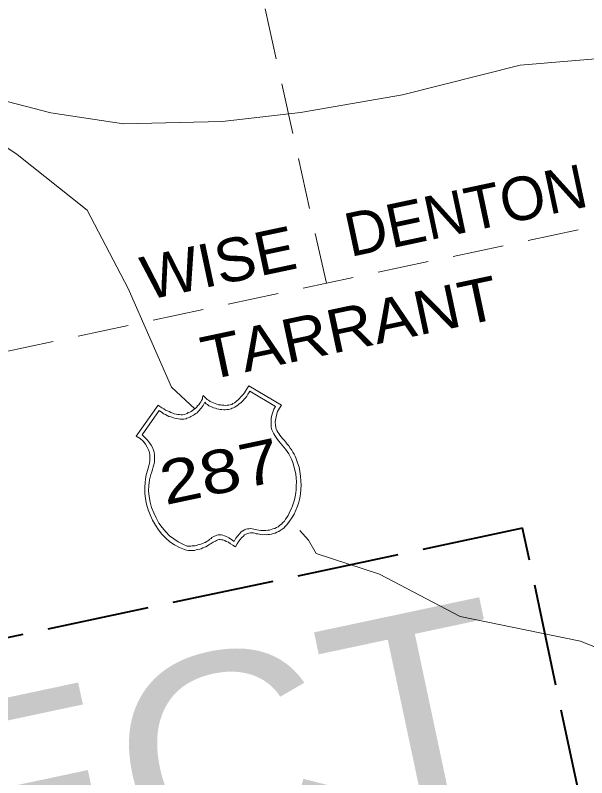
# Model space of a CAD drawing. Extents: x 2357218 to 2371708, y 6973728 to 6980157.
# Drawn here: x 2357388.5 to 2357455.6, y 6974746.8 to 6974836.3 of the extents above; entities that cross this region are included whole.
import ezdxf

# ---------------------------------------------------------------- set-up
doc = ezdxf.new("R2010")
doc.units = 0
doc.header["$LTSCALE"] = 2
doc.linetypes.add('LONG_DASHED', pattern=[7.5, 6, -1.5])
doc.linetypes.add('MEDIUM_DASHED', pattern=[4.5, 3, -1.5])
doc.layers.add('62', color=7, linetype='Continuous', lineweight=13)
doc.layers.add('63', color=7, linetype='Continuous', lineweight=13)

msp = doc.modelspace()

# ---------------------------------------------------------------- linework, layer by layer
at = {"layer": '62', "linetype": 'MEDIUM_DASHED'}
for p, q in [((2357425, 6974804.799), (2357404.314, 6974897.367)), ((2357701.055, 6974863.476), (2357262.587, 6974770.278))]:
    msp.add_line(p, q, dxfattribs=at)
at = {"layer": '62'}
for p, q in [((2357406.798, 6974792.604), (2357409.547, 6974790.06)), ((2357422.92, 6974774.658), (2357421.873, 6974775.793))]:
    msp.add_line(p, q, dxfattribs=at)
for points in [[(2357340.901, 6974883.89), (2357347.602, 6974879.103), (2357357.079, 6974868.946), (2357365.551, 6974857.313), (2357370.799, 6974843.455), (2357373.187, 6974835.471), (2357378.836, 6974826.528), (2357388.708, 6974819.907), (2357396.909, 6974813.368), (2357401.732, 6974804.203), (2357406.798, 6974792.604)], [(2357316.634, 6974822.183), (2357325.977, 6974829.21), (2357339.57, 6974833.985), (2357356.843, 6974830.109), (2357367.736, 6974831.46), (2357382.508, 6974827.444), (2357392.662, 6974824.794), (2357401.195, 6974823.527), (2357412.755, 6974823.776), (2357421.962, 6974824.837), (2357433.942, 6974826.923), (2357447.739, 6974830.408), (2357465.936, 6974831.929), (2357477.637, 6974833.588), (2357491.11, 6974834.819), (2357506.983, 6974831.471), (2357522.127, 6974827.953), (2357536.104, 6974824.115), (2357552.75, 6974816.152), (2357563.852, 6974811.216), (2357577.192, 6974806.369), (2357585.353, 6974801.086)], [(2357402.679, 6974786.874), (2357405.245, 6974790.503), (2357405.462, 6974790.341), (2357405.682, 6974790.181), (2357405.914, 6974790.069), (2357406.102, 6974789.926), (2357406.329, 6974789.838), (2357406.534, 6974789.741), (2357406.738, 6974789.647), (2357406.963, 6974789.557), (2357407.143, 6974789.479), (2357407.355, 6974789.456), (2357407.546, 6974789.404), (2357407.755, 6974789.403), (2357407.945, 6974789.374), (2357408.108, 6974789.364), (2357408.33, 6974789.411), (2357408.523, 6974789.474), (2357408.649, 6974789.523), (2357408.791, 6974789.623), (2357408.963, 6974789.681), (2357409.128, 6974789.762), (2357409.283, 6974789.889), (2357409.425, 6974789.988), (2357409.583, 6974790.113), (2357409.74, 6974790.239), (2357409.867, 6974790.404), (2357410.019, 6974790.551), (2357410.142, 6974790.736), (2357410.272, 6974790.881), (2357410.347, 6974791.058), (2357410.45, 6974791.239), (2357410.476, 6974791.431), (2357410.547, 6974791.63), (2357410.695, 6974791.478), (2357410.843, 6974791.323), (2357411.013, 6974791.177), (2357411.172, 6974791.072), (2357411.364, 6974790.929), (2357411.562, 6974790.856), (2357411.746, 6974790.756), (2357411.948, 6974790.685), (2357412.141, 6974790.634), (2357412.319, 6974790.555), (2357412.552, 6974790.537), (2357412.718, 6974790.504), (2357412.972, 6974790.512), (2357413.139, 6974790.477), (2357413.369, 6974790.482), (2357413.545, 6974790.519), (2357413.7, 6974790.55), (2357413.898, 6974790.592), (2357414.014, 6974790.687), (2357414.204, 6974790.774), (2357414.362, 6974790.899), (2357414.501, 6974790.996), (2357414.632, 6974791.141), (2357414.806, 6974791.292), (2357414.937, 6974791.436), (2357415.085, 6974791.605), (2357415.214, 6974791.769), (2357415.376, 6974791.965), (2357415.498, 6974792.153), (2357415.641, 6974792.345), (2357415.756, 6974792.553), (2357415.897, 6974792.767), (2357419.715, 6974790.495), (2357419.488, 6974790.147), (2357419.273, 6974789.756), (2357419.154, 6974789.342), (2357419.081, 6974788.937), (2357419.006, 6974788.528), (2357419.017, 6974788.162), (2357419.076, 6974787.875), (2357419.118, 6974787.678), (2357419.193, 6974787.532), (2357419.302, 6974787.347), (2357419.406, 6974787.187), (2357419.541, 6974786.985), (2357419.696, 6974786.786), (2357419.853, 6974786.592), (2357420.04, 6974786.379), (2357420.225, 6974786.142), (2357420.41, 6974785.926), (2357420.592, 6974785.712), (2357420.764, 6974785.451), (2357420.926, 6974785.232), (2357421.072, 6974784.987), (2357421.209, 6974784.764), (2357421.327, 6974784.534), (2357421.422, 6974784.303), (2357421.61, 6974783.745), (2357421.793, 6974783.208), (2357421.901, 6974782.702), (2357421.947, 6974782.157), (2357422.012, 6974781.64), (2357422.029, 6974781.117), (2357422.001, 6974780.605), (2357421.95, 6974780.088), (2357421.894, 6974779.591), (2357421.766, 6974779.105)], [(2357420.765, 6974778.088), (2357420.912, 6974778.371), (2357421.025, 6974778.694), (2357421.138, 6974779.039), (2357421.245, 6974779.409), (2357421.323, 6974779.794), (2357421.396, 6974780.2), (2357421.443, 6974780.624), (2357421.47, 6974781.046), (2357421.486, 6974781.507), (2357421.439, 6974781.959), (2357421.41, 6974782.413), (2357421.308, 6974782.896), (2357421.185, 6974783.355), (2357421.049, 6974783.785), (2357420.924, 6974784.15), (2357420.74, 6974784.48), (2357420.582, 6974784.791), (2357420.385, 6974785.07), (2357420.208, 6974785.356), (2357420.021, 6974785.592), (2357419.81, 6974785.823), (2357419.6, 6974786.054), (2357419.419, 6974786.268), (2357419.256, 6974786.488), (2357419.093, 6974786.706), (2357418.932, 6974786.927), (2357418.814, 6974787.153), (2357418.703, 6974787.359), (2357418.602, 6974787.614), (2357418.51, 6974787.938), (2357418.506, 6974788.284), (2357418.502, 6974788.629), (2357418.518, 6974788.976), (2357418.582, 6974789.333), (2357418.694, 6974789.681), (2357418.85, 6974790.015), (2357419.011, 6974790.346), (2357416.005, 6974792.146), (2357415.885, 6974791.957), (2357415.783, 6974791.776), (2357415.667, 6974791.567), (2357415.543, 6974791.402), (2357415.395, 6974791.232), (2357415.247, 6974791.063), (2357415.094, 6974790.917), (2357414.942, 6974790.768), (2357414.763, 6974790.639), (2357414.608, 6974790.492), (2357414.425, 6974790.383), (2357414.261, 6974790.279), (2357414.096, 6974790.199), (2357413.946, 6974790.142), (2357413.803, 6974790.066), (2357413.65, 6974790.034), (2357413.494, 6974790), (2357413.313, 6974789.985), (2357413.11, 6974789.967), (2357412.952, 6974789.953), (2357412.718, 6974789.975), (2357412.55, 6974790.007), (2357412.362, 6974790.037), (2357412.143, 6974790.082), (2357411.972, 6974790.137), (2357411.754, 6974790.182), (2357411.597, 6974790.266), (2357411.421, 6974790.344), (2357411.215, 6974790.437), (2357411.049, 6974790.563), (2357410.89, 6974790.667), (2357410.717, 6974790.839), (2357410.622, 6974790.632), (2357410.523, 6974790.451), (2357410.418, 6974790.29), (2357410.311, 6974790.153), (2357410.175, 6974790.032), (2357410.088, 6974789.901), (2357409.938, 6974789.75), (2357409.826, 6974789.613), (2357409.683, 6974789.535), (2357409.526, 6974789.409), (2357409.402, 6974789.339), (2357409.24, 6974789.234), (2357409.09, 6974789.181), (2357408.952, 6974789.081), (2357408.78, 6974789.023), (2357408.63, 6974788.966), (2357408.483, 6974788.911), (2357408.262, 6974788.864), (2357408.054, 6974788.868), (2357407.826, 6974788.866), (2357407.634, 6974788.895), (2357407.394, 6974788.934), (2357407.154, 6974788.975), (2357406.98, 6974789.054), (2357406.736, 6974789.116), (2357406.515, 6974789.185), (2357406.309, 6974789.28), (2357406.124, 6974789.4), (2357405.896, 6974789.489), (2357405.706, 6974789.634)], [(2357405.379, 6974789.863), (2357403.36, 6974787.018), (2357403.699, 6974786.723), (2357404, 6974786.396), (2357404.224, 6974786.099), (2357404.443, 6974785.822), (2357404.575, 6974785.529), (2357404.707, 6974785.234), (2357404.784, 6974784.976), (2357404.824, 6974784.684), (2357404.818, 6974784.384), (2357404.831, 6974784.11), (2357404.804, 6974783.807), (2357404.729, 6974783.515), (2357404.669, 6974783.249), (2357404.594, 6974782.957), (2357404.491, 6974782.682), (2357404.392, 6974782.384), (2357404.228, 6974781.752), (2357404.164, 6974781.072), (2357404.133, 6974780.467), (2357404.209, 6974779.794), (2357404.326, 6974779.126), (2357404.484, 6974778.492), (2357404.734, 6974777.852), (2357404.998, 6974777.266), (2357405.331, 6974776.671), (2357405.722, 6974776.13), (2357406.152, 6974775.626), (2357406.591, 6974775.167), (2357407.084, 6974774.811), (2357407.594, 6974774.46), (2357408.137, 6974774.184), (2357408.666, 6974773.975), (2357408.781, 6974773.975), (2357408.928, 6974773.937), (2357409.085, 6974773.949), (2357409.261, 6974773.985), (2357409.399, 6974773.992), (2357409.58, 6974774.006), (2357409.756, 6974774.043), (2357409.925, 6974774.104), (2357410.12, 6974774.169), (2357410.274, 6974774.201), (2357410.463, 6974774.286), (2357410.634, 6974774.346), (2357410.784, 6974774.402), (2357410.946, 6974774.504), (2357411.089, 6974774.58), (2357411.215, 6974774.654), (2357411.325, 6974774.769), (2357411.466, 6974774.867), (2357411.563, 6974774.957), (2357411.702, 6974775.057), (2357411.847, 6974775.132), (2357411.973, 6974775.183), (2357412.123, 6974775.239), (2357412.278, 6974775.271), (2357412.437, 6974775.281), (2357412.644, 6974775.281), (2357412.834, 6974775.252), (2357413.038, 6974775.157), (2357413.281, 6974775.092), (2357413.549, 6974774.919), (2357413.859, 6974774.755), (2357414.163, 6974774.52), (2357414.383, 6974774.89), (2357414.6, 6974775.165), (2357414.801, 6974775.415), (2357415.009, 6974775.62), (2357415.189, 6974775.752), (2357415.373, 6974775.861), (2357415.54, 6974775.941), (2357415.759, 6974775.988), (2357415.918, 6974775.997), (2357416.079, 6974776.011), (2357416.289, 6974775.984), (2357416.479, 6974775.957), (2357416.647, 6974775.924), (2357416.844, 6974775.873), (2357417.054, 6974775.848), (2357417.27, 6974775.802), (2357417.479, 6974775.8), (2357417.691, 6974775.778), (2357417.893, 6974775.797), (2357418.119, 6974775.823), (2357418.321, 6974775.841), (2357418.535, 6974775.911), (2357418.73, 6974775.975), (2357418.944, 6974776.044), (2357419.152, 6974776.157), (2357419.34, 6974776.242), (2357419.531, 6974776.422), (2357419.712, 6974776.552), (2357419.881, 6974776.727), (2357420.072, 6974776.905), (2357420.211, 6974777.118), (2357420.373, 6974777.336), (2357420.512, 6974777.549), (2357420.636, 6974777.83), (2357420.765, 6974778.088)], [(2357405.706, 6974789.634), (2357405.54, 6974789.76), (2357405.379, 6974789.863)], [(2357403.476, 6974786.263), (2357403.132, 6974786.58), (2357402.679, 6974786.874)], [(2357421.766, 6974779.105), (2357421.614, 6974778.636), (2357421.413, 6974778.179), (2357421.231, 6974777.727), (2357420.934, 6974777.295), (2357420.678, 6974776.872), (2357420.351, 6974776.459), (2357420.165, 6974776.258), (2357419.993, 6974776.083), (2357419.793, 6974775.949), (2357419.593, 6974775.813), (2357419.414, 6974775.683), (2357419.202, 6974775.591), (2357418.969, 6974775.498), (2357418.778, 6974775.432), (2357418.538, 6974775.358), (2357418.312, 6974775.334), (2357418.11, 6974775.315), (2357417.929, 6974775.3), (2357417.698, 6974775.318), (2357417.515, 6974775.304), (2357417.323, 6974775.331), (2357417.131, 6974775.382), (2357416.945, 6974775.389), (2357416.755, 6974775.418), (2357416.603, 6974775.478), (2357416.413, 6974775.506), (2357416.279, 6974775.501), (2357416.092, 6974775.506), (2357415.909, 6974775.49), (2357415.759, 6974775.458), (2357415.59, 6974775.377), (2357415.406, 6974775.269), (2357415.256, 6974775.122), (2357415.079, 6974774.97), (2357414.898, 6974774.748), (2357414.714, 6974774.523), (2357414.527, 6974774.21), (2357414.326, 6974773.867), (2357414.004, 6974774.074), (2357413.738, 6974774.248), (2357413.492, 6974774.424), (2357413.245, 6974774.511), (2357413.06, 6974774.61), (2357412.863, 6974774.683), (2357412.694, 6974774.716), (2357412.531, 6974774.725), (2357412.395, 6974774.721), (2357412.24, 6974774.687), (2357412.114, 6974774.638), (2357411.969, 6974774.561), (2357411.864, 6974774.516), (2357411.72, 6974774.44), (2357411.578, 6974774.341), (2357411.456, 6974774.268), (2357411.337, 6974774.175), (2357411.192, 6974774.097), (2357411.03, 6974773.993), (2357410.848, 6974773.887), (2357410.677, 6974773.827), (2357410.489, 6974773.741), (2357410.296, 6974773.654), (2357410.125, 6974773.594), (2357409.908, 6974773.548), (2357409.708, 6974773.506), (2357409.511, 6974773.464), (2357409.262, 6974773.434), (2357409.052, 6974773.458), (2357408.822, 6974773.454), (2357408.58, 6974773.497), (2357408.338, 6974773.558), (2357407.762, 6974773.783), (2357407.189, 6974774.097), (2357406.629, 6974774.46), (2357406.147, 6974774.888), (2357405.678, 6974775.364), (2357405.274, 6974775.853), (2357404.926, 6974776.421), (2357404.591, 6974777.017), (2357404.3, 6974777.624), (2357404.081, 6974778.223), (2357403.896, 6974778.872), (2357403.76, 6974779.512), (2357403.686, 6974780.187), (2357403.669, 6974780.805), (2357403.71, 6974781.48), (2357403.815, 6974782.078), (2357403.855, 6974782.317), (2357403.917, 6974782.561), (2357403.999, 6974782.83), (2357404.079, 6974783.099), (2357404.155, 6974783.393), (2357404.233, 6974783.684), (2357404.279, 6974783.994), (2357404.285, 6974784.295), (2357404.288, 6974784.617), (2357404.216, 6974784.946), (2357404.129, 6974785.249), (2357403.966, 6974785.584), (2357403.756, 6974785.907), (2357403.476, 6974786.263)], [(2357422.92, 6974774.658), (2357423.803, 6974773.097), (2357431.242, 6974770.675), (2357440.696, 6974765.714), (2357454.819, 6974762.805), (2357466.769, 6974757.982), (2357474.201, 6974755.812)]]:
    msp.add_lwpolyline(points, dxfattribs=at)
at = {"layer": '62', "linetype": 'LONG_DASHED', "lineweight": 40}
msp.add_lwpolyline([(2357277.991, 6974739.919), (2357291.257, 6974677.497), (2357461.31, 6974713.643), (2357448.042, 6974776.064), (2357277.682, 6974739.853)], dxfattribs=at)
at = {"layer": '63', "linetype": 'MEDIUM_DASHED'}
for p, q in [((2357425, 6974804.799), (2357404.314, 6974897.367)), ((2357701.055, 6974863.476), (2357262.587, 6974770.278))]:
    msp.add_line(p, q, dxfattribs=at)
at = {"layer": '63'}
for p, q in [((2357406.798, 6974792.604), (2357409.547, 6974790.06)), ((2357422.92, 6974774.658), (2357421.873, 6974775.793))]:
    msp.add_line(p, q, dxfattribs=at)
for points in [[(2357340.901, 6974883.89), (2357347.602, 6974879.103), (2357357.079, 6974868.946), (2357365.551, 6974857.313), (2357370.799, 6974843.455), (2357373.187, 6974835.471), (2357378.836, 6974826.528), (2357388.708, 6974819.907), (2357396.909, 6974813.368), (2357401.732, 6974804.203), (2357406.798, 6974792.604)], [(2357316.634, 6974822.183), (2357325.977, 6974829.21), (2357339.57, 6974833.985), (2357356.843, 6974830.109), (2357367.736, 6974831.46), (2357382.508, 6974827.444), (2357392.662, 6974824.794), (2357401.195, 6974823.527), (2357412.755, 6974823.776), (2357421.962, 6974824.837), (2357433.942, 6974826.923), (2357447.739, 6974830.408), (2357465.936, 6974831.929), (2357477.637, 6974833.588), (2357491.11, 6974834.819), (2357506.983, 6974831.471), (2357522.127, 6974827.953), (2357536.104, 6974824.115), (2357552.75, 6974816.152), (2357563.852, 6974811.216), (2357577.192, 6974806.369), (2357585.353, 6974801.086)], [(2357402.679, 6974786.874), (2357405.245, 6974790.503), (2357405.462, 6974790.341), (2357405.682, 6974790.181), (2357405.914, 6974790.069), (2357406.102, 6974789.926), (2357406.329, 6974789.838), (2357406.534, 6974789.741), (2357406.738, 6974789.647), (2357406.963, 6974789.557), (2357407.143, 6974789.479), (2357407.355, 6974789.456), (2357407.546, 6974789.404), (2357407.755, 6974789.403), (2357407.945, 6974789.374), (2357408.108, 6974789.364), (2357408.33, 6974789.411), (2357408.523, 6974789.474), (2357408.649, 6974789.523), (2357408.791, 6974789.623), (2357408.963, 6974789.681), (2357409.128, 6974789.762), (2357409.283, 6974789.889), (2357409.425, 6974789.988), (2357409.583, 6974790.113), (2357409.74, 6974790.239), (2357409.867, 6974790.404), (2357410.019, 6974790.551), (2357410.142, 6974790.736), (2357410.272, 6974790.881), (2357410.347, 6974791.058), (2357410.45, 6974791.239), (2357410.476, 6974791.431), (2357410.547, 6974791.63), (2357410.695, 6974791.478), (2357410.843, 6974791.323), (2357411.013, 6974791.177), (2357411.172, 6974791.072), (2357411.364, 6974790.929), (2357411.562, 6974790.856), (2357411.746, 6974790.756), (2357411.948, 6974790.685), (2357412.141, 6974790.634), (2357412.319, 6974790.555), (2357412.552, 6974790.537), (2357412.718, 6974790.504), (2357412.972, 6974790.512), (2357413.139, 6974790.477), (2357413.369, 6974790.482), (2357413.545, 6974790.519), (2357413.7, 6974790.55), (2357413.898, 6974790.592), (2357414.014, 6974790.687), (2357414.204, 6974790.774), (2357414.362, 6974790.899), (2357414.501, 6974790.996), (2357414.632, 6974791.141), (2357414.806, 6974791.292), (2357414.937, 6974791.436), (2357415.085, 6974791.605), (2357415.214, 6974791.769), (2357415.376, 6974791.965), (2357415.498, 6974792.153), (2357415.641, 6974792.345), (2357415.756, 6974792.553), (2357415.897, 6974792.767), (2357419.715, 6974790.495), (2357419.488, 6974790.147), (2357419.273, 6974789.756), (2357419.154, 6974789.342), (2357419.081, 6974788.937), (2357419.006, 6974788.528), (2357419.017, 6974788.162), (2357419.076, 6974787.875), (2357419.118, 6974787.678), (2357419.193, 6974787.532), (2357419.302, 6974787.347), (2357419.406, 6974787.187), (2357419.541, 6974786.985), (2357419.696, 6974786.786), (2357419.853, 6974786.592), (2357420.04, 6974786.379), (2357420.225, 6974786.142), (2357420.41, 6974785.926), (2357420.592, 6974785.712), (2357420.764, 6974785.451), (2357420.926, 6974785.232), (2357421.072, 6974784.987), (2357421.209, 6974784.764), (2357421.327, 6974784.534), (2357421.422, 6974784.303), (2357421.61, 6974783.745), (2357421.793, 6974783.208), (2357421.901, 6974782.702), (2357421.947, 6974782.157), (2357422.012, 6974781.64), (2357422.029, 6974781.117), (2357422.001, 6974780.605), (2357421.95, 6974780.088), (2357421.894, 6974779.591), (2357421.766, 6974779.105)], [(2357420.765, 6974778.088), (2357420.912, 6974778.371), (2357421.025, 6974778.694), (2357421.138, 6974779.039), (2357421.245, 6974779.409), (2357421.323, 6974779.794), (2357421.396, 6974780.2), (2357421.443, 6974780.624), (2357421.47, 6974781.046), (2357421.486, 6974781.507), (2357421.439, 6974781.959), (2357421.41, 6974782.413), (2357421.308, 6974782.896), (2357421.185, 6974783.355), (2357421.049, 6974783.785), (2357420.924, 6974784.15), (2357420.74, 6974784.48), (2357420.582, 6974784.791), (2357420.385, 6974785.07), (2357420.208, 6974785.356), (2357420.021, 6974785.592), (2357419.81, 6974785.823), (2357419.6, 6974786.054), (2357419.419, 6974786.268), (2357419.256, 6974786.488), (2357419.093, 6974786.706), (2357418.932, 6974786.927), (2357418.814, 6974787.153), (2357418.703, 6974787.359), (2357418.602, 6974787.614), (2357418.51, 6974787.938), (2357418.506, 6974788.284), (2357418.502, 6974788.629), (2357418.518, 6974788.976), (2357418.582, 6974789.333), (2357418.694, 6974789.681), (2357418.85, 6974790.015), (2357419.011, 6974790.346), (2357416.005, 6974792.146), (2357415.885, 6974791.957), (2357415.783, 6974791.776), (2357415.667, 6974791.567), (2357415.543, 6974791.402), (2357415.395, 6974791.232), (2357415.247, 6974791.063), (2357415.094, 6974790.917), (2357414.942, 6974790.768), (2357414.763, 6974790.639), (2357414.608, 6974790.492), (2357414.425, 6974790.383), (2357414.261, 6974790.279), (2357414.096, 6974790.199), (2357413.946, 6974790.142), (2357413.803, 6974790.066), (2357413.65, 6974790.034), (2357413.494, 6974790), (2357413.313, 6974789.985), (2357413.11, 6974789.967), (2357412.952, 6974789.953), (2357412.718, 6974789.975), (2357412.55, 6974790.007), (2357412.362, 6974790.037), (2357412.143, 6974790.082), (2357411.972, 6974790.137), (2357411.754, 6974790.182), (2357411.597, 6974790.266), (2357411.421, 6974790.344), (2357411.215, 6974790.437), (2357411.049, 6974790.563), (2357410.89, 6974790.667), (2357410.717, 6974790.839), (2357410.622, 6974790.632), (2357410.523, 6974790.451), (2357410.418, 6974790.29), (2357410.311, 6974790.153), (2357410.175, 6974790.032), (2357410.088, 6974789.901), (2357409.938, 6974789.75), (2357409.826, 6974789.613), (2357409.683, 6974789.535), (2357409.526, 6974789.409), (2357409.402, 6974789.339), (2357409.24, 6974789.234), (2357409.09, 6974789.181), (2357408.952, 6974789.081), (2357408.78, 6974789.023), (2357408.63, 6974788.966), (2357408.483, 6974788.911), (2357408.262, 6974788.864), (2357408.054, 6974788.868), (2357407.826, 6974788.866), (2357407.634, 6974788.895), (2357407.394, 6974788.934), (2357407.154, 6974788.975), (2357406.98, 6974789.054), (2357406.736, 6974789.116), (2357406.515, 6974789.185), (2357406.309, 6974789.28), (2357406.124, 6974789.4), (2357405.896, 6974789.489), (2357405.706, 6974789.634)], [(2357405.379, 6974789.863), (2357403.36, 6974787.018), (2357403.699, 6974786.723), (2357404, 6974786.396), (2357404.224, 6974786.099), (2357404.443, 6974785.822), (2357404.575, 6974785.529), (2357404.707, 6974785.234), (2357404.784, 6974784.976), (2357404.824, 6974784.684), (2357404.818, 6974784.384), (2357404.831, 6974784.11), (2357404.804, 6974783.807), (2357404.729, 6974783.515), (2357404.669, 6974783.249), (2357404.594, 6974782.957), (2357404.491, 6974782.682), (2357404.392, 6974782.384), (2357404.228, 6974781.752), (2357404.164, 6974781.072), (2357404.133, 6974780.467), (2357404.209, 6974779.794), (2357404.326, 6974779.126), (2357404.484, 6974778.492), (2357404.734, 6974777.852), (2357404.998, 6974777.266), (2357405.331, 6974776.671), (2357405.722, 6974776.13), (2357406.152, 6974775.626), (2357406.591, 6974775.167), (2357407.084, 6974774.811), (2357407.594, 6974774.46), (2357408.137, 6974774.184), (2357408.666, 6974773.975), (2357408.781, 6974773.975), (2357408.928, 6974773.937), (2357409.085, 6974773.949), (2357409.261, 6974773.985), (2357409.399, 6974773.992), (2357409.58, 6974774.006), (2357409.756, 6974774.043), (2357409.925, 6974774.104), (2357410.12, 6974774.169), (2357410.274, 6974774.201), (2357410.463, 6974774.286), (2357410.634, 6974774.346), (2357410.784, 6974774.402), (2357410.946, 6974774.504), (2357411.089, 6974774.58), (2357411.215, 6974774.654), (2357411.325, 6974774.769), (2357411.466, 6974774.867), (2357411.563, 6974774.957), (2357411.702, 6974775.057), (2357411.847, 6974775.132), (2357411.973, 6974775.183), (2357412.123, 6974775.239), (2357412.278, 6974775.271), (2357412.437, 6974775.281), (2357412.644, 6974775.281), (2357412.834, 6974775.252), (2357413.038, 6974775.157), (2357413.281, 6974775.092), (2357413.549, 6974774.919), (2357413.859, 6974774.755), (2357414.163, 6974774.52), (2357414.383, 6974774.89), (2357414.6, 6974775.165), (2357414.801, 6974775.415), (2357415.009, 6974775.62), (2357415.189, 6974775.752), (2357415.373, 6974775.861), (2357415.54, 6974775.941), (2357415.759, 6974775.988), (2357415.918, 6974775.997), (2357416.079, 6974776.011), (2357416.289, 6974775.984), (2357416.479, 6974775.957), (2357416.647, 6974775.924), (2357416.844, 6974775.873), (2357417.054, 6974775.848), (2357417.27, 6974775.802), (2357417.479, 6974775.8), (2357417.691, 6974775.778), (2357417.893, 6974775.797), (2357418.119, 6974775.823), (2357418.321, 6974775.841), (2357418.535, 6974775.911), (2357418.73, 6974775.975), (2357418.944, 6974776.044), (2357419.152, 6974776.157), (2357419.34, 6974776.242), (2357419.531, 6974776.422), (2357419.712, 6974776.552), (2357419.881, 6974776.727), (2357420.072, 6974776.905), (2357420.211, 6974777.118), (2357420.373, 6974777.336), (2357420.512, 6974777.549), (2357420.636, 6974777.83), (2357420.765, 6974778.088)], [(2357405.706, 6974789.634), (2357405.54, 6974789.76), (2357405.379, 6974789.863)], [(2357403.476, 6974786.263), (2357403.132, 6974786.58), (2357402.679, 6974786.874)], [(2357421.766, 6974779.105), (2357421.614, 6974778.636), (2357421.413, 6974778.179), (2357421.231, 6974777.727), (2357420.934, 6974777.295), (2357420.678, 6974776.872), (2357420.351, 6974776.459), (2357420.165, 6974776.258), (2357419.993, 6974776.083), (2357419.793, 6974775.949), (2357419.593, 6974775.813), (2357419.414, 6974775.683), (2357419.202, 6974775.591), (2357418.969, 6974775.498), (2357418.778, 6974775.432), (2357418.538, 6974775.358), (2357418.312, 6974775.334), (2357418.11, 6974775.315), (2357417.929, 6974775.3), (2357417.698, 6974775.318), (2357417.515, 6974775.304), (2357417.323, 6974775.331), (2357417.131, 6974775.382), (2357416.945, 6974775.389), (2357416.755, 6974775.418), (2357416.603, 6974775.478), (2357416.413, 6974775.506), (2357416.279, 6974775.501), (2357416.092, 6974775.506), (2357415.909, 6974775.49), (2357415.759, 6974775.458), (2357415.59, 6974775.377), (2357415.406, 6974775.269), (2357415.256, 6974775.122), (2357415.079, 6974774.97), (2357414.898, 6974774.748), (2357414.714, 6974774.523), (2357414.527, 6974774.21), (2357414.326, 6974773.867), (2357414.004, 6974774.074), (2357413.738, 6974774.248), (2357413.492, 6974774.424), (2357413.245, 6974774.511), (2357413.06, 6974774.61), (2357412.863, 6974774.683), (2357412.694, 6974774.716), (2357412.531, 6974774.725), (2357412.395, 6974774.721), (2357412.24, 6974774.687), (2357412.114, 6974774.638), (2357411.969, 6974774.561), (2357411.864, 6974774.516), (2357411.72, 6974774.44), (2357411.578, 6974774.341), (2357411.456, 6974774.268), (2357411.337, 6974774.175), (2357411.192, 6974774.097), (2357411.03, 6974773.993), (2357410.848, 6974773.887), (2357410.677, 6974773.827), (2357410.489, 6974773.741), (2357410.296, 6974773.654), (2357410.125, 6974773.594), (2357409.908, 6974773.548), (2357409.708, 6974773.506), (2357409.511, 6974773.464), (2357409.262, 6974773.434), (2357409.052, 6974773.458), (2357408.822, 6974773.454), (2357408.58, 6974773.497), (2357408.338, 6974773.558), (2357407.762, 6974773.783), (2357407.189, 6974774.097), (2357406.629, 6974774.46), (2357406.147, 6974774.888), (2357405.678, 6974775.364), (2357405.274, 6974775.853), (2357404.926, 6974776.421), (2357404.591, 6974777.017), (2357404.3, 6974777.624), (2357404.081, 6974778.223), (2357403.896, 6974778.872), (2357403.76, 6974779.512), (2357403.686, 6974780.187), (2357403.669, 6974780.805), (2357403.71, 6974781.48), (2357403.815, 6974782.078), (2357403.855, 6974782.317), (2357403.917, 6974782.561), (2357403.999, 6974782.83), (2357404.079, 6974783.099), (2357404.155, 6974783.393), (2357404.233, 6974783.684), (2357404.279, 6974783.994), (2357404.285, 6974784.295), (2357404.288, 6974784.617), (2357404.216, 6974784.946), (2357404.129, 6974785.249), (2357403.966, 6974785.584), (2357403.756, 6974785.907), (2357403.476, 6974786.263)], [(2357422.92, 6974774.658), (2357423.803, 6974773.097), (2357431.242, 6974770.675), (2357440.696, 6974765.714), (2357454.819, 6974762.805), (2357466.769, 6974757.982), (2357474.201, 6974755.812)]]:
    msp.add_lwpolyline(points, dxfattribs=at)
at = {"layer": '63', "linetype": 'LONG_DASHED', "lineweight": 40}
msp.add_lwpolyline([(2357277.991, 6974739.919), (2357291.257, 6974677.497), (2357461.31, 6974713.643), (2357448.042, 6974776.064), (2357277.682, 6974739.853)], dxfattribs=at)

# ---------------------------------------------------------------- texts
at = {"layer": '62'}
msp.add_text('DENTON', height=5.099, rotation=12, dxfattribs=at).set_placement((2357427.799, 6974807.879))
for s, height, width, p in [('WISE', 5.099, 1.05, (2357403.919, 6974802.804)), ('TARRANT', 5.099, 1.1, (2357410.955, 6974793.394)), ('287', 5.099, 1.25, (2357406.082, 6974778.765)), ('PROJECT', 23.83, 1.1, (2357288.665, 6974710.81))]:
    msp.add_text(s, height=height, rotation=12, dxfattribs=dict(at, width=width)).set_placement(p)
at = {"layer": '63'}
msp.add_text('DENTON', height=5.099, rotation=12, dxfattribs=at).set_placement((2357427.799, 6974807.879))
for s, height, width, p in [('WISE', 5.099, 1.05, (2357403.919, 6974802.804)), ('TARRANT', 5.099, 1.1, (2357410.955, 6974793.394)), ('287', 5.099, 1.25, (2357406.082, 6974778.765)), ('PROJECT', 23.83, 1.1, (2357288.665, 6974710.81))]:
    msp.add_text(s, height=height, rotation=12, dxfattribs=dict(at, width=width)).set_placement(p)

doc.saveas('drawing.dxf')
